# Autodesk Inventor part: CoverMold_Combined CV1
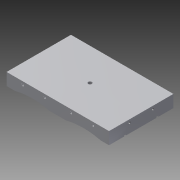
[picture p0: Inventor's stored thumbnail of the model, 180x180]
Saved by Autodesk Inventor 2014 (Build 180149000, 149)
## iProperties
Created: 2009-12
Part Number: CoverMold_Combined CV1
Document SubType Name: Modeling
Designer: gaom
Density: 1 g/cm^3
Material: Generic
Appearance: Default
Author: gaom
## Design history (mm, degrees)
node "CoverMold_AsmContainer" dims "d0" = 10
sketch "Sketch1"
  geometry: L1 (0, 0)-(0, -440) reference; L2 (700, 0)-(0, 0) reference; L3 (700, -440)-(700, 0) reference; L4 (0, -440)-(700, -440) reference; L5 (0, 0)-(0, -440) reference; L6 (700, 0)-(0, 0) reference; L7 (700, -440)-(700, 0) reference; L8 (0, -440)-(700, -440) reference; L9 (0, 0)-(0, -440) reference; L10 (700, 0)-(0, 0) reference; L11 (700, -440)-(700, 0) reference; L12 (0, -440)-(700, -440) reference; L13 (0, 0)-(0, -440) reference; L14 (700, 0)-(0, 0) reference; L15 (700, -440)-(700, 0) reference; L16 (0, -440)-(700, -440) reference; L17 (0, 0)-(700, 0); L18 (700, 0)-(700, -440); L19 (700, -440)-(0, -440); L20 (0, -440)-(0, 0)
  constraints: 8 end point, 2 parallel, 1 horizontal, 1 perpendicular
sketch "Sketch2"
  geometry: L1 (0, 0)-(0, -440) reference; L2 (700, 0)-(0, 0) reference; L3 (700, -440)-(700, 0) reference; L4 (0, -440)-(700, -440) reference
sketch "Sketch3"
  geometry: L1 (0, 0)-(0, -440) reference; L2 (700, 0)-(0, 0) reference; L3 (700, -440)-(700, 0) reference; L4 (0, -440)-(700, -440) reference
sketch "Sketch4"
  geometry: L1 (0, 0)-(0, -440) reference; L2 (700, 0)-(0, 0) reference; L3 (700, -440)-(700, 0) reference; L4 (0, -440)-(700, -440) reference
sketch "Sketch5"
  geometry: L1 (0, 0)-(0, -440) reference; L2 (700, 0)-(0, 0) reference; L3 (700, -440)-(700, 0) reference; L4 (0, -440)-(700, -440) reference
feature "Sculpt1"
feature "Sculpt2"
thread "Thread1" dims "d1" = 0, "d2" = 0
feature "Sculpt3"
thread "Thread2" dims "d3" = 0, "d4" = 0
feature "Sculpt4"
thread "Thread3" dims "d5" = 0, "d6" = 0
feature "Sculpt5"
thread "Thread4" dims "d7" = 0, "d8" = 0
feature "Sculpt6"
feature "Sculpt7"
feature "Sculpt8"
feature "Sculpt9"
feature "Sculpt10"
feature "Sculpt11"
feature "Sculpt12"
feature "Sculpt13"
feature "Sculpt14"
feature "Sculpt15"
feature "Sculpt16"
feature "Sculpt17"
feature "Sculpt18"
feature "Sculpt19"
feature "Sculpt20"
feature "Sculpt21"
feature "Sculpt22"
body "Solid1"
node "CoverMold_cover_CV_1:1" dims "d0" = 10
node "CoverMold_cover_CV_2:1" dims "d0" = 10
node "CoverMold_cover_CV_3:1" dims "d0" = 10
node "CoverMold_cover_CV_4:1" dims "d0" = 10
feature "Surface1"
body "Srf1"
feature "Surface2"
body "Srf2"
feature "Surface3"
body "Srf3"
feature "Surface4"
body "Srf4"
feature "Surface5"
body "Srf5"
feature "Surface6"
body "Srf6"
feature "Surface7"
body "Srf7"
feature "Surface8"
body "Srf8"
feature "Surface9"
body "Srf9"
feature "Surface10"
body "Srf10"
feature "Surface11"
body "Srf11"
feature "Surface12"
body "Srf12"
feature "Surface13"
body "Srf13"
feature "Surface14"
body "Srf14"
feature "Surface15"
body "Srf15"
feature "Surface16"
body "Srf16"
feature "Surface17"
body "Srf17"
feature "Surface18"
body "Srf18"
feature "Surface19"
body "Srf19"
feature "Surface20"
body "Srf20"
feature "Surface21"
body "Srf21"
feature "Surface22"
body "Srf22"
